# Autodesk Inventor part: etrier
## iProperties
Created: 2001-11
Part Number: etrier
Material: Par défaut
Document SubType Name: Tôlerie
Designer: BAVERGE
Control State: 0
Master: False
Checked Out: False
Shininess: 60.0
Length Units: 11269
Angle Units: 11279
Time Units: 11290
Mass Units: 11283
Length Display Precision: 3
Angle Display Precision: 2
Density: 0.0
Volumn: 0.0
Area: 0.0
PropertySet Name: Model Information
Author: BAVERGE
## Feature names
1. Chanfrein de coin1
2. Arrondi de coin1
3. Chanfrein de coin2
4. Arrondi de coin2
5. Perçage1 [Hole]
6. Perçage2 [Hole]
7. Perçage3 [Hole]
8. Arrondi de coin3
9. Ouverture1
10. Extrusion1
11. Congé1 [Fillet]
12. Ouverture2
13. Extrusion3
14. Plaque1
15. Plaque2
16. Pli1
17. Plaque3
18. Pli2
